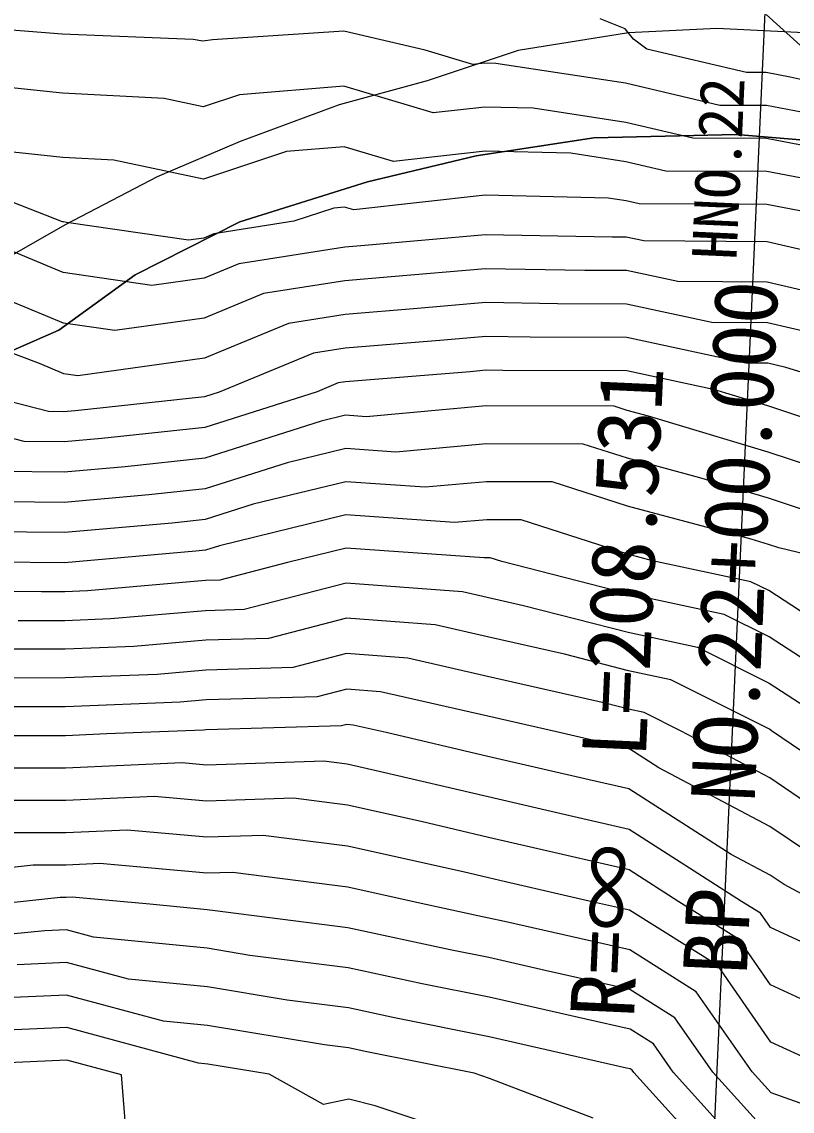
# Model space of a CAD drawing. Extents: x 42655 to 43811, y -141820 to -141156.
# Drawn here: x 43620.52 to 43648.36, y -141406.29 to -141366.92 of the extents above; entities that cross this region are included whole.
import ezdxf

# ---------------------------------------------------------------- set-up
doc = ezdxf.new("R2010")
doc.units = 0
for name, color, linetype in [('D-BMK-HTXT_1', 7, 'Continuous'), ('ZE_HICN', 7, 'Continuous'), ('ZE_LWCN', 7, 'Continuous'), ('地形', 7, 'Continuous'), ('現況道路ﾊｯﾁ', 7, 'Continuous')]:
    doc.layers.add(name, color=color, linetype=linetype)

msp = doc.modelspace()

# ---------------------------------------------------------------- linework, layer by layer
at = {"layer": 'D-BMK-HTXT_1'}
msp.add_line((43648.124, -141349.997), (43644.54, -141428.915), dxfattribs=at)
at = {"layer": 'ZE_HICN'}
for points in [[(43651.818, -141373.165), (43647.441, -141372.335), (43643.798, -141372.318), (43642.351, -141371.979), (43640.357, -141371.673), (43637.261, -141371.6), (43633.947, -141371.969), (43632.172, -141371.436), (43630.087, -141371.608), (43627.089, -141372.608), (43623.846, -141371.925), (43621.997, -141371.824), (43619.864, -141371.6)], [(43650.689, -141380.199), (43648.13, -141379.416), (43647.474, -141379.263), (43646.68, -141379.257), (43642.381, -141378.329), (43638.89, -141378.321), (43637.293, -141378.294), (43635.771, -141378.426), (43632.206, -141378.716), (43631.056, -141378.898), (43627.656, -141380.308), (43627.127, -141380.477), (43622.564, -141380.966), (43622.041, -141381.013), (43621.489, -141381.007), (43618.945, -141380.35)], [(43649.494, -141388.76), (43647.513, -141387.479), (43646.87, -141387.156), (43643.31, -141386.397), (43642.418, -141386.159), (43638.562, -141384.92), (43637.324, -141384.915), (43636.161, -141385.021), (43632.235, -141384.744), (43627.659, -141385.858), (43627.153, -141386.019), (43626.807, -141386.056), (43622.067, -141386.476), (43617.059, -141386.424)], [(43648.982, -141396.97), (43647.553, -141395.998), (43643.545, -141393.879), (43642.451, -141393.178), (43642.026, -141393.08), (43639.842, -141392.576), (43637.358, -141392.014), (43633.485, -141391.129), (43632.265, -141391.036), (43631.191, -141391.315), (43627.179, -141391.427), (43626.245, -141391.509), (43622.092, -141391.673), (43617.833, -141391.676)], [(43651.041, -141406.849), (43647.599, -141405.629), (43646.911, -141404.868), (43644.894, -141401.97), (43642.486, -141400.46), (43637.963, -141399.438), (43637.392, -141399.308), (43636.998, -141399.229), (43634.846, -141398.762), (43632.299, -141398.197), (43628.144, -141397.66), (43627.208, -141397.691), (43623.336, -141397.343), (43622.119, -141397.396), (43620.936, -141397.396), (43617.033, -141397.826)], [(43637.431, -141407.483), (43633.294, -141406.092), (43632.335, -141405.855), (43631.428, -141406.042), (43629.459, -141404.951), (43627.241, -141404.585), (43626.902, -141404.552), (43622.147, -141403.268), (43618.354, -141403.435), (43617.06, -141403.561), (43615.938, -141403.656), (43611.967, -141402.638), (43608.053, -141403.637), (43606.884, -141403.585), (43605.8, -141403.749), (43601.801, -141404.702), (43597.749, -141403.841), (43596.709, -141403.93), (43592.493, -141404.071), (43591.621, -141404.054), (43590.818, -141404.16), (43589.93, -141405.138), (43588.468, -141408.993)]]:
    msp.add_lwpolyline(points, dxfattribs=at)
at = {"layer": 'ZE_LWCN'}
for points in [[(43685.824, -141382.577), (43684.581, -141381.828), (43683.099, -141380.993), (43682.574, -141380.682), (43681.687, -141380.052), (43677.998, -141378.275), (43676.006, -141377.67), (43672.904, -141377.133), (43670.866, -141376.406), (43667.803, -141374.47), (43667.218, -141373.958), (43664.181, -141372.184), (43662.7, -141371.196), (43659.876, -141370.576), (43657.606, -141369.999), (43656.175, -141369.578), (43652.512, -141368.717), (43648.78, -141367.883), (43647.414, -141366.657)], [(43649.459, -141370.336), (43647.429, -141369.951), (43645.74, -141369.944), (43642.337, -141369.146), (43637.65, -141368.425), (43637.246, -141368.415), (43636.813, -141368.463), (43635.094, -141367.948), (43632.152, -141367.262), (43627.407, -141367.571), (43627.066, -141367.623), (43626.715, -141367.563), (43621.976, -141367.371), (43617.709, -141367.034)], [(43685.824, -141384.347), (43683.108, -141382.816), (43681.572, -141381.907), (43678.981, -141380.065), (43678.004, -141379.594), (43677.477, -141379.434), (43672.911, -141378.643), (43669.911, -141377.573), (43667.812, -141376.246), (43665.207, -141373.967), (43663.525, -141372.985), (43662.706, -141372.439), (43661.142, -141372.095), (43657.612, -141371.198), (43655.386, -141370.543), (43652.517, -141369.869), (43648.28, -141368.922), (43647.424, -141368.759), (43646.711, -141368.756), (43643.101, -141367.91), (43642.629, -141367.549), (43642.328, -141367.178), (43641.42, -141366.82)], [(43650.638, -141371.75), (43647.435, -141371.143), (43644.769, -141371.131), (43642.344, -141370.563), (43639.003, -141370.049), (43637.253, -141370.008), (43635.38, -141370.216), (43632.161, -141369.251), (43628.381, -141369.561), (43627.077, -141369.997), (43625.666, -141369.699), (43621.986, -141369.498), (43617.741, -141369.053)], [(43650.146, -141374.039), (43647.446, -141373.527), (43642.827, -141373.506), (43642.358, -141373.396), (43641.711, -141373.296), (43637.268, -141373.192), (43632.514, -141373.721), (43632.182, -141373.622), (43631.792, -141373.654), (43630.356, -141374.133), (43627.465, -141374.59), (43627.099, -141374.742), (43626.549, -141374.818), (43622.13, -141374.172), (43622.027, -141374.15), (43622.008, -141374.149), (43621.987, -141374.147), (43616.911, -141372.166)], [(43651.142, -141375.734), (43647.453, -141374.871), (43642.999, -141374.841), (43642.364, -141374.704), (43641.848, -141374.703), (43637.275, -141374.626), (43632.917, -141375.003), (43632.189, -141375.062), (43628.362, -141375.667), (43627.106, -141376.188), (43625.215, -141376.45), (43622.017, -141375.983), (43617.703, -141374.193)], [(43650.138, -141376.961), (43647.46, -141376.335), (43644.226, -141376.313), (43642.369, -141375.913), (43640.862, -141375.909), (43637.281, -141375.849), (43633.868, -141376.144), (43632.195, -141376.28), (43629.26, -141376.744), (43627.113, -141377.635), (43623.88, -141378.082), (43622.026, -141377.812), (43618.828, -141376.485)], [(43649.134, -141378.189), (43647.467, -141377.799), (43645.453, -141377.785), (43642.375, -141377.121), (43639.876, -141377.115), (43637.287, -141377.071), (43634.819, -141377.285), (43632.201, -141377.498), (43630.158, -141377.821), (43627.12, -141379.081), (43622.545, -141379.715), (43622.035, -141379.64), (43621.154, -141379.275), (43616.937, -141377.68)], [(43651.087, -141381.999), (43647.481, -141380.799), (43645.563, -141380.223), (43642.387, -141379.538), (43637.903, -141379.527), (43637.298, -141379.517), (43636.722, -141379.567), (43632.212, -141379.934), (43631.954, -141379.974), (43631.189, -141380.292), (43627.132, -141381.586), (43623.413, -141381.984), (43622.046, -141382.105), (43620.603, -141382.09), (43616.954, -141381.148)], [(43650.015, -141383.31), (43647.489, -141382.469), (43643.169, -141381.173), (43642.393, -141380.965), (43641.92, -141380.813), (43637.305, -141380.798), (43632.969, -141381.193), (43632.218, -141381.14), (43631.342, -141381.353), (43627.137, -141382.694), (43624.261, -141383.002), (43622.051, -141383.198), (43619.717, -141383.174)], [(43648.944, -141384.62), (43647.497, -141384.139), (43645.023, -141383.397), (43642.402, -141382.697), (43640.801, -141382.182), (43637.311, -141382.17), (43634.033, -141382.469), (43632.224, -141382.341), (43630.114, -141382.855), (43627.142, -141383.802), (43625.11, -141384.02), (43622.057, -141384.291), (43618.831, -141384.257)], [(43649.67, -141386.367), (43647.872, -141385.931), (43647.505, -141385.809), (43646.877, -141385.621), (43642.41, -141384.428), (43639.682, -141383.551), (43637.318, -141383.543), (43635.097, -141383.745), (43632.229, -141383.542), (43628.886, -141384.356), (43627.148, -141384.911), (43625.959, -141385.038), (43622.062, -141385.383), (43617.945, -141385.341)], [(43652.504, -141392.371), (43647.521, -141389.149), (43645.905, -141388.337), (43642.425, -141387.595), (43637.861, -141386.423), (43637.443, -141386.288), (43637.331, -141386.288), (43637.225, -141386.298), (43632.241, -141385.945), (43630.127, -141386.459), (43627.674, -141387.096), (43627.158, -141387.11), (43622.889, -141387.484), (43622.072, -141387.516), (43621.234, -141387.517), (43616.984, -141387.476)], [(43620.384, -141388.556), (43622.077, -141388.555), (43623.728, -141388.49), (43627.163, -141388.19), (43628.553, -141388.15), (43632.247, -141387.192), (43636.444, -141387.511), (43637.337, -141387.715), (43638.655, -141388.013), (43642.432, -141388.983), (43644.939, -141389.517), (43647.528, -141390.819), (43650.17, -141392.527)], [(43650.822, -141394.72), (43647.613, -141392.539), (43647.536, -141392.489), (43643.974, -141390.698), (43642.438, -141390.371), (43640.125, -141389.777), (43637.344, -141389.148), (43635.458, -141388.717), (43632.253, -141388.474), (43629.432, -141389.205), (43627.168, -141389.269), (43624.567, -141389.496), (43622.082, -141389.595), (43619.533, -141389.596)], [(43649.902, -141395.845), (43647.545, -141394.242), (43644.352, -141392.554), (43643.009, -141391.879), (43642.445, -141391.759), (43641.596, -141391.54), (43637.351, -141390.581), (43634.472, -141389.923), (43632.259, -141389.755), (43630.312, -141390.26), (43627.174, -141390.348), (43625.406, -141390.503), (43622.087, -141390.634), (43618.683, -141390.636)], [(43649.192, -141398.694), (43648.063, -141398.094), (43647.561, -141397.754), (43646.156, -141397.011), (43642.458, -141394.642), (43641.02, -141394.31), (43637.365, -141393.466), (43633.682, -141392.605), (43632.499, -141392.335), (43632.271, -141392.317), (43632.07, -141392.369), (43627.184, -141392.507), (43627.084, -141392.515), (43623.593, -141392.653), (43622.097, -141392.719), (43617.038, -141392.719)], [(43648.852, -141400.245), (43647.57, -141399.653), (43647.211, -141399.136), (43646.526, -141398.707), (43642.465, -141396.106), (43640.015, -141395.54), (43637.372, -141394.93), (43633.438, -141394.01), (43632.278, -141393.753), (43631.429, -141393.643), (43627.19, -141393.783), (43626.312, -141393.704), (43622.102, -141393.888), (43618.012, -141393.889)], [(43651.649, -141403.599), (43647.58, -141401.721), (43646.438, -141400.081), (43644.264, -141398.718), (43642.472, -141397.57), (43639.009, -141396.77), (43637.379, -141396.394), (43634.952, -141395.826), (43632.285, -141395.234), (43630.334, -141394.982), (43627.196, -141395.085), (43625.32, -141394.917), (43622.108, -141395.057), (43618.987, -141395.058)], [(43649.896, -141404.854), (43647.59, -141403.789), (43645.666, -141401.025), (43642.479, -141399.027), (43641.175, -141398.732), (43638.003, -141398), (43637.386, -141397.857), (43636.466, -141397.642), (43632.292, -141396.715), (43629.239, -141396.321), (43627.202, -141396.388), (43624.328, -141396.13), (43622.113, -141396.227), (43619.962, -141396.227)], [(43647.606, -141407.221), (43645.486, -141404.874), (43644.121, -141402.915), (43642.493, -141401.893), (43639.434, -141401.202), (43637.399, -141400.738), (43635.995, -141400.457), (43632.306, -141399.657), (43627.416, -141399.041), (43627.215, -141399.008), (43625.151, -141398.808), (43622.344, -141398.556), (43622.124, -141398.566), (43621.911, -141398.566), (43619.46, -141398.835)], [(43647.614, -141408.814), (43644.061, -141404.881), (43643.349, -141403.859), (43642.5, -141403.326), (43640.904, -141402.966), (43637.406, -141402.168), (43634.991, -141401.684), (43632.313, -141401.103), (43628.762, -141400.656), (43627.221, -141400.402), (43623.111, -141400.005), (43622.13, -141399.74), (43621.347, -141399.775), (43617.044, -141400.194)], [(43647.622, -141410.406), (43642.635, -141404.888), (43642.577, -141404.804), (43642.507, -141404.76), (43642.375, -141404.73), (43637.413, -141403.597), (43633.987, -141402.912), (43632.32, -141402.55), (43630.109, -141402.272), (43627.228, -141401.796), (43624.375, -141401.521), (43622.136, -141400.916), (43620.35, -141400.995)], [(43641.161, -141406.535), (43637.42, -141405.103), (43636.861, -141404.915), (43632.983, -141404.139), (43632.327, -141403.997), (43631.456, -141403.887), (43627.235, -141403.19), (43625.638, -141403.036), (43622.141, -141402.092), (43619.352, -141402.215), (43617.055, -141402.439), (43615.064, -141402.607), (43611.963, -141401.812), (43608.907, -141402.591), (43606.879, -141402.502), (43604.998, -141402.787), (43601.795, -141403.55), (43598.55, -141402.861), (43596.705, -141403.018), (43593.259, -141403.134), (43591.617, -141403.101), (43590.102, -141403.302), (43588.43, -141405.145), (43586.562, -141410.069)], [(43624.402, -141408.435), (43624.122, -141404.976), (43622.152, -141404.444), (43617.356, -141404.656), (43617.065, -141404.684), (43616.813, -141404.705), (43611.971, -141403.464), (43607.198, -141404.682), (43606.889, -141404.668), (43606.602, -141404.711), (43605.112, -141405.066), (43601.812, -141407.002), (43598.252, -141405.099), (43596.947, -141404.822), (43596.713, -141404.842), (43591.726, -141405.008), (43591.626, -141405.006), (43591.533, -141405.019), (43591.431, -141405.131), (43591.263, -141405.575), (43588.866, -141411.306)]]:
    msp.add_lwpolyline(points, dxfattribs=at)
at = {"layer": '地形'}
for points in [[(43671.768, -141347.675), (43670.95, -141351.434), (43670.051, -141355.52), (43669.805, -141358.258), (43669.846, -141359.851), (43670.051, -141365.122), (43670.133, -141369.045), (43666.943, -141368.677), (43664.04, -141368.391), (43660.36, -141368.105), (43657.253, -141368.105), (43653.409, -141367.819), (43649.77, -141367.37), (43645.641, -141367.165), (43642.447, -141367.327), (43638.461, -141367.962), (43635.169, -141369.058), (43631.993, -141369.924), (43628.412, -141371.252), (43625.408, -141372.521), (43622.116, -141374.253), (43619.459, -141375.754)], [(43685.824, -141380.415), (43685.409, -141380.275), (43680.538, -141378.754), (43676.351, -141376.396), (43672.85, -141374.038), (43671.176, -141372.441), (43666.998, -141371.821), (43662.173, -141371.458), (43657.943, -141371.326), (43652.226, -141371.491), (43646.344, -141370.996), (43641.187, -141371.12), (43636.939, -141371.773), (43633.018, -141372.706), (43628.397, -141374.152), (43624.616, -141376.064), (43621.862, -141378.07), (43618.734, -141379.423)]]:
    msp.add_lwpolyline(points, dxfattribs=at)
at = {"layer": '現況道路ﾊｯﾁ'}
for points in [[(43649.77, -141367.37), (43645.641, -141367.165), (43642.447, -141367.327), (43638.461, -141367.962), (43635.169, -141369.058), (43631.993, -141369.924), (43628.412, -141371.252), (43625.408, -141372.521), (43622.116, -141374.253), (43619.459, -141375.754)], [(43618.734, -141379.423), (43621.862, -141378.07), (43624.616, -141376.064), (43628.397, -141374.152), (43633.018, -141372.706), (43636.939, -141371.773), (43641.187, -141371.12), (43646.344, -141370.996), (43652.226, -141371.491)]]:
    msp.add_lwpolyline(points, dxfattribs=at)

# ---------------------------------------------------------------- texts
at = {"layer": 'D-BMK-HTXT_1'}
for s, p in [('BP  NO.22+00.000', (43646.715, -141401.411)), ('R=∞  L=208.531', (43642.639, -141402.951))]:
    msp.add_text(s, height=2.30651, rotation=87.3991, dxfattribs=at).set_placement(p)
at = {"layer": '地形'}
msp.add_text('HNO.22', height=1.612, rotation=87.395, dxfattribs=at).set_placement((43646.343, -141375.544))

doc.saveas('drawing.dxf')
